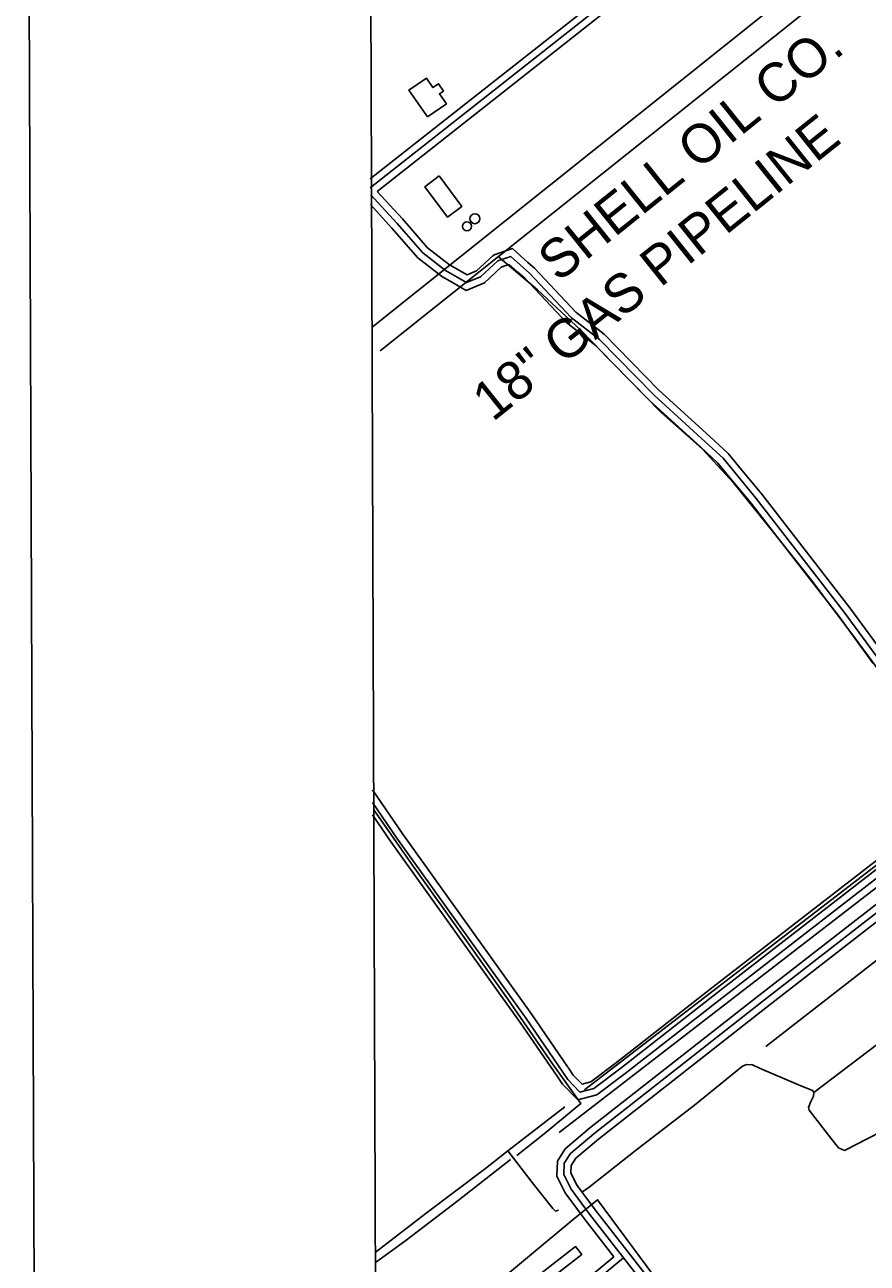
# Model space of a CAD drawing. Extents: x 3405885 to 3443815, y 558517 to 583997.
# Drawn here: x 3409221 to 3411021, y 577623 to 580269 of the extents above; entities that cross this region are included whole.
import ezdxf

# ---------------------------------------------------------------- set-up
doc = ezdxf.new("R2010")
doc.units = 0
for name, color, linetype in [('V-ANNO-SYMB', 7, 'Continuous'), ('V-BLDG-OTLN', 7, 'Continuous'), ('V-DOMW-TANK', 7, 'Continuous'), ('V-DTCH-CNTR', 7, 'Continuous'), ('V-GRID-FRAM', 7, 'Continuous'), ('V-ROAD-CNTR', 7, 'Continuous'), ('V-SITE-OTLN', 7, 'Continuous'), ('V-TOPO-SHOR', 7, 'Continuous'), ('V-UTIL-IDEN', 7, 'Continuous'), ('V-UTIL-LINE', 7, 'Continuous')]:
    doc.layers.add(name, color=color, linetype=linetype)

msp = doc.modelspace()

# ---------------------------------------------------------------- linework, layer by layer
at = {"layer": 'V-ANNO-SYMB'}
msp.add_lwpolyline([(3409312.5, 559736.2), (3442395.5, 559868.5), (3442303.8, 582784.9), (3409220.9, 582652.6), (3409312.5, 559736.2)], dxfattribs=at)
at = {"layer": 'V-BLDG-OTLN'}
for points in [[(3410081.2, 580072), (3410041.7, 580129.2), (3410078.9, 580154.9), (3410092.8, 580134.7), (3410104.6, 580142.9), (3410115.3, 580127.4), (3410106.8, 580121.5), (3410121.7, 580099.9)], [(3410106.6, 579946.5), (3410155, 579880.9), (3410123.9, 579858), (3410076, 579923)], [(3410271.4, 577560.9), (3410397.9, 577658.9), (3410411.1, 577641.9), (3410284.4, 577543.8)]]:
    msp.add_lwpolyline(points, close=True, dxfattribs=at)
at = {"layer": 'V-DOMW-TANK'}
for centre, radius in [((3410182.6, 579854.6), 10.6), ((3410165.7, 579838.4), 9.39)]:
    msp.add_circle(centre, radius, dxfattribs=at)
at = {"layer": 'V-DTCH-CNTR'}
for points in [[(3410232.3, 579774), (3410316.2, 579702.8), (3410408.8, 579616.6), (3410477.4, 579546), (3410580.3, 579440.7), (3410668.1, 579362.8), (3410735, 579290.5), (3410819.3, 579186.4), (3410900.9, 579082.8), (3410992.2, 578962.1), (3411080.2, 578843.2), (3411192.1, 578687.3), (3411268.7, 578584.8), (3411290.4, 578553.5), (3411329.6, 578502.8)], [(3409966.5, 578592.1), (3410047.5, 578476.2), (3410152.3, 578329.1), (3410253.3, 578187), (3410348.3, 578049.4), (3410409.2, 577964.6), (3410330.9, 577899.8), (3410272.5, 577853.6)], [(3410258.7, 577845), (3410146.9, 577757.4), (3410035, 577671.6), (3409969.9, 577624.7)]]:
    msp.add_lwpolyline(points, dxfattribs=at)
at = {"layer": 'V-GRID-FRAM'}
msp.add_lwpolyline([(3409954, 582088.9), (3441575.2, 582215.4), (3441655.9, 564032.2), (3410018.8, 563905.7), (3409954, 582088.9)], dxfattribs=at)
at = {"layer": 'V-ROAD-CNTR'}
for points in [[(3410469.8, 580342.2), (3409959.1, 579939.6)], [(3410479.1, 580330.5), (3409959.2, 579920.5)], [(3410488.4, 580318.7), (3409973.9, 579913)], [(3409959.7, 579906.4), (3410016.6, 579844.6), (3410071.1, 579781.8), (3410119.9, 579743.9), (3410164.8, 579718), (3410194.6, 579730.5), (3410231.3, 579764.4), (3410259.4, 579773.6), (3410299.4, 579738.2), (3410388.3, 579643.8), (3410448.8, 579596.6), (3410565.5, 579477.5), (3410674.5, 579378.2), (3410712.9, 579342.8), (3410783.8, 579256.8), (3410856.9, 579162.5), (3410971.9, 579014.2), (3411089.4, 578853.5), (3411196.3, 578699), (3411250, 578626.7)], [(3409973.9, 579913), (3410027.7, 579854.6), (3410081.5, 579792.7), (3410128.3, 579756.4), (3410139.7, 579749.8)], [(3409959.3, 579884.6), (3410005.4, 579834.6), (3410060.8, 579770.8), (3410111.5, 579731.5), (3410112, 579731.2)], [(3410139.7, 579749.8), (3410165.9, 579734.7), (3410186.4, 579743.3), (3410221.1, 579775.4)], [(3410221.1, 579775.4), (3410223.5, 579777.6), (3410262.9, 579790.6), (3410295.8, 579761.4)], [(3410129.7, 579721), (3410163.7, 579701.3), (3410202.9, 579717.7), (3410239.1, 579751.2), (3410248.8, 579754.4)], [(3410248.8, 579754.4), (3410255.9, 579756.7), (3410274.6, 579740.1)], [(3410295.8, 579761.4), (3410309.9, 579749), (3410398.4, 579654.9), (3410458.8, 579607.8), (3410575.9, 579488.3), (3410684.6, 579389.2), (3410723.8, 579353.1), (3410753.2, 579317.5)], [(3410112, 579731.2), (3410129.7, 579721)], [(3410274.6, 579740.1), (3410289, 579727.4), (3410378.2, 579632.7), (3410438.8, 579585.4), (3410555.1, 579466.7), (3410664.4, 579367.1), (3410702, 579332.5), (3410734.8, 579292.7)], [(3410729.8, 577348.3), (3410593.5, 577515.1), (3410427.7, 577728.1), (3410388.1, 577781.4), (3410372.8, 577812.5), (3410373.7, 577836.8), (3410386.6, 577857.6), (3410437.1, 577900), (3410795.1, 578180.8), (3411245.4, 578530.4), (3411873.5, 579019.9), (3412386.4, 579417.5), (3412669.1, 579639.2), (3412713.8, 579669.1), (3412750.2, 579689.7), (3412768.7, 579699.8)], [(3410732.2, 577369.2), (3410605.2, 577524.5), (3410439.7, 577737.1), (3410401, 577789.3), (3410387.9, 577815.7), (3410388.6, 577832.2), (3410398.1, 577847.7), (3410446.5, 577888.4), (3410804.3, 578169), (3411254.6, 578518.5), (3411882.7, 579008.1), (3412395.6, 579405.7), (3412677.9, 579627.1), (3412721.7, 579656.3), (3412757.5, 579676.6), (3412775.9, 579686.6)], [(3412606.9, 579590.4), (3412578.5, 579599.1), (3412541.6, 579597.4), (3412522.6, 579589.5), (3412360.5, 579471.2), (3412185.3, 579345.2), (3411899.8, 579129.6), (3411612, 578906.3), (3411188.9, 578579.6), (3410700.8, 578201.5), (3410494.4, 578040.1), (3410436.8, 577996.8), (3410407.1, 577989), (3410381.3, 578015.4), (3410292, 578146.2), (3410016.1, 578531.1), (3409963.9, 578607.5)], [(3410479.5, 577637.1), (3410415.8, 577719), (3410375.3, 577773.5), (3410357.6, 577809.3), (3410358.9, 577841.3), (3410375.2, 577867.6), (3410427.6, 577911.7), (3410785.8, 578192.6), (3411236.2, 578542.2), (3411864.2, 579031.8), (3412377.2, 579429.4), (3412574.2, 579583.9)], [(3410753.2, 579317.5), (3410795.5, 579266.2), (3410868.8, 579171.7), (3410983.9, 579023.2), (3411052.6, 578929.2)], [(3410734.8, 579292.7), (3410772.1, 579247.5), (3410845.1, 579153.3), (3410959.9, 579005.2), (3411033.6, 578904.4)], [(3410381.2, 578042.1), (3410304.3, 578154.8), (3410028.4, 578539.7), (3409963.8, 578634.2)], [(3411229.1, 578629.6), (3411179.7, 578591.4), (3410691.6, 578213.4), (3410485.3, 578052), (3410430.1, 578010.6), (3410411.8, 578005.7), (3410392.9, 578025), (3410381.8, 578041.2)], [(3411242.5, 578602), (3411198.1, 578567.7), (3410710, 578189.7), (3410503.5, 578028.2), (3410443.4, 577983.1), (3410416.4, 577975.9)], [(3410358.1, 578022.7), (3410279.7, 578137.6), (3410003.9, 578522.5), (3409964, 578580.8)], [(3410416.4, 577975.9), (3410402.5, 577972.3), (3410369.6, 578005.9), (3410358.1, 578022.7)], [(3410689.3, 577374.2), (3410510.6, 577239.8), (3410377.4, 577127.5), (3410334.1, 577097.8), (3410310.2, 577093.6), (3410273.3, 577100.2), (3410229.4, 577143.9), (3410166.8, 577225.2), (3410122.5, 577284.2), (3410113.4, 577327.5), (3410135.1, 577372.1), (3410163.4, 577396.4), (3410371.3, 577547.5), (3410479.5, 577637.1)], [(3410691.8, 577394.9), (3410501.2, 577251.5), (3410368.3, 577139.5), (3410328.3, 577112), (3410310.2, 577108.8), (3410280.5, 577114.1), (3410240.7, 577153.8), (3410178.7, 577234.2), (3410136.5, 577290.6), (3410129.1, 577325.6), (3410147.2, 577362.8), (3410172.7, 577384.6), (3410380.5, 577535.6), (3410500.3, 577634.8), (3410501, 577633.5)]]:
    msp.add_lwpolyline(points, dxfattribs=at)
at = {"layer": 'V-SITE-OTLN'}
msp.add_lwpolyline([(3410201.7, 577557.7), (3410392.4, 577716.3), (3410444.8, 577758.9), (3410595.5, 577555.1)], dxfattribs=at)
at = {"layer": 'V-TOPO-SHOR'}
for p, q in [((3409980.5, 579572.7), (3411278.3, 580607.3)), ((3410907.1, 577987.8), (3412652.1, 579316.9)), ((3410362.6, 577902.8), (3412089.2, 579235.9)), ((3410416.8, 577993.9), (3411231.8, 578620.9)), ((3410252.8, 577863.6), (3410374.5, 577957.4))]:
    msp.add_line(p, q, dxfattribs=at)
for points in [[(3410804, 578086.3), (3412440, 579358.4), (3412687.5, 579547.2)], [(3410972, 577864.2), (3411101.3, 577930), (3412755.3, 579238.6)], [(3410972, 577864.2), (3410959.7, 577870.1), (3410943.4, 577890.2), (3410896.9, 577950.3), (3410895.1, 577956.2), (3410900.5, 577968.5), (3410906.4, 577980.2), (3410907.1, 577987.8), (3410904.2, 577992.5), (3410873.7, 578004.4), (3410790.7, 578039.6), (3410776.1, 578047.3), (3410763.2, 578048), (3410754.3, 578044.5), (3410651.7, 577960.7), (3410525, 577863), (3410426.5, 577785.6), (3410410.6, 577774.6)], [(3410361.1, 577736.8), (3410354.6, 577734.5), (3410348.8, 577739.8), (3410305.1, 577795.8), (3410272, 577838.3), (3410252.8, 577863.6), (3410205, 577825.8), (3410078.3, 577730.4), (3409969.8, 577646)]]:
    msp.add_lwpolyline(points, dxfattribs=at)
at = {"layer": 'V-UTIL-LINE'}
msp.add_lwpolyline([(3409962.8, 579622.7), (3411098, 580529.2), (3411124.3, 580811), (3411173.2, 581356.4), (3412086.7, 582097.4)], dxfattribs=at)

# ---------------------------------------------------------------- texts
at = {"layer": 'V-UTIL-IDEN'}
for s, rotation, p in [('SHELL OIL CO.', 38.8046, (3410361, 579717.2)), ('18" GAS PIPELINE', 38.7072, (3410220.8, 579419.4))]:
    msp.add_text(s, height=83, rotation=rotation, dxfattribs=at).set_placement(p)

doc.saveas('drawing.dxf')
